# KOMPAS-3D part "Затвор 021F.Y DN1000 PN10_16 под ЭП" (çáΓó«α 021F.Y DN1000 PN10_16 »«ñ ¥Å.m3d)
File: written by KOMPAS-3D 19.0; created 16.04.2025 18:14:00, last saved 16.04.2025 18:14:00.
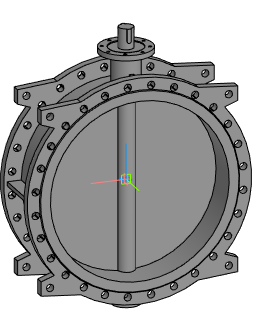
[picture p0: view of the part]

Document properties: Автор: Евгений; Полное имя файла: E:\Dendor Работа Сачек\3D для проекитирвщиков\1.6 Тип 021F.Y Затвор дисковый поворотный фланцевый\stp_Тип 021F.Y Затвор  DN40 PN10_16 под ЭП\Затвор 021F.Y DN1000 PN10_16 под ЭП.m3d

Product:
- Part/product: Затвор 021F.Y DN1000 PN10_16 под ЭП

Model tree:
1. Операция без истории:1  (labels: Затвор 021F.Y DN1000 PN10_16 под ЭП)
